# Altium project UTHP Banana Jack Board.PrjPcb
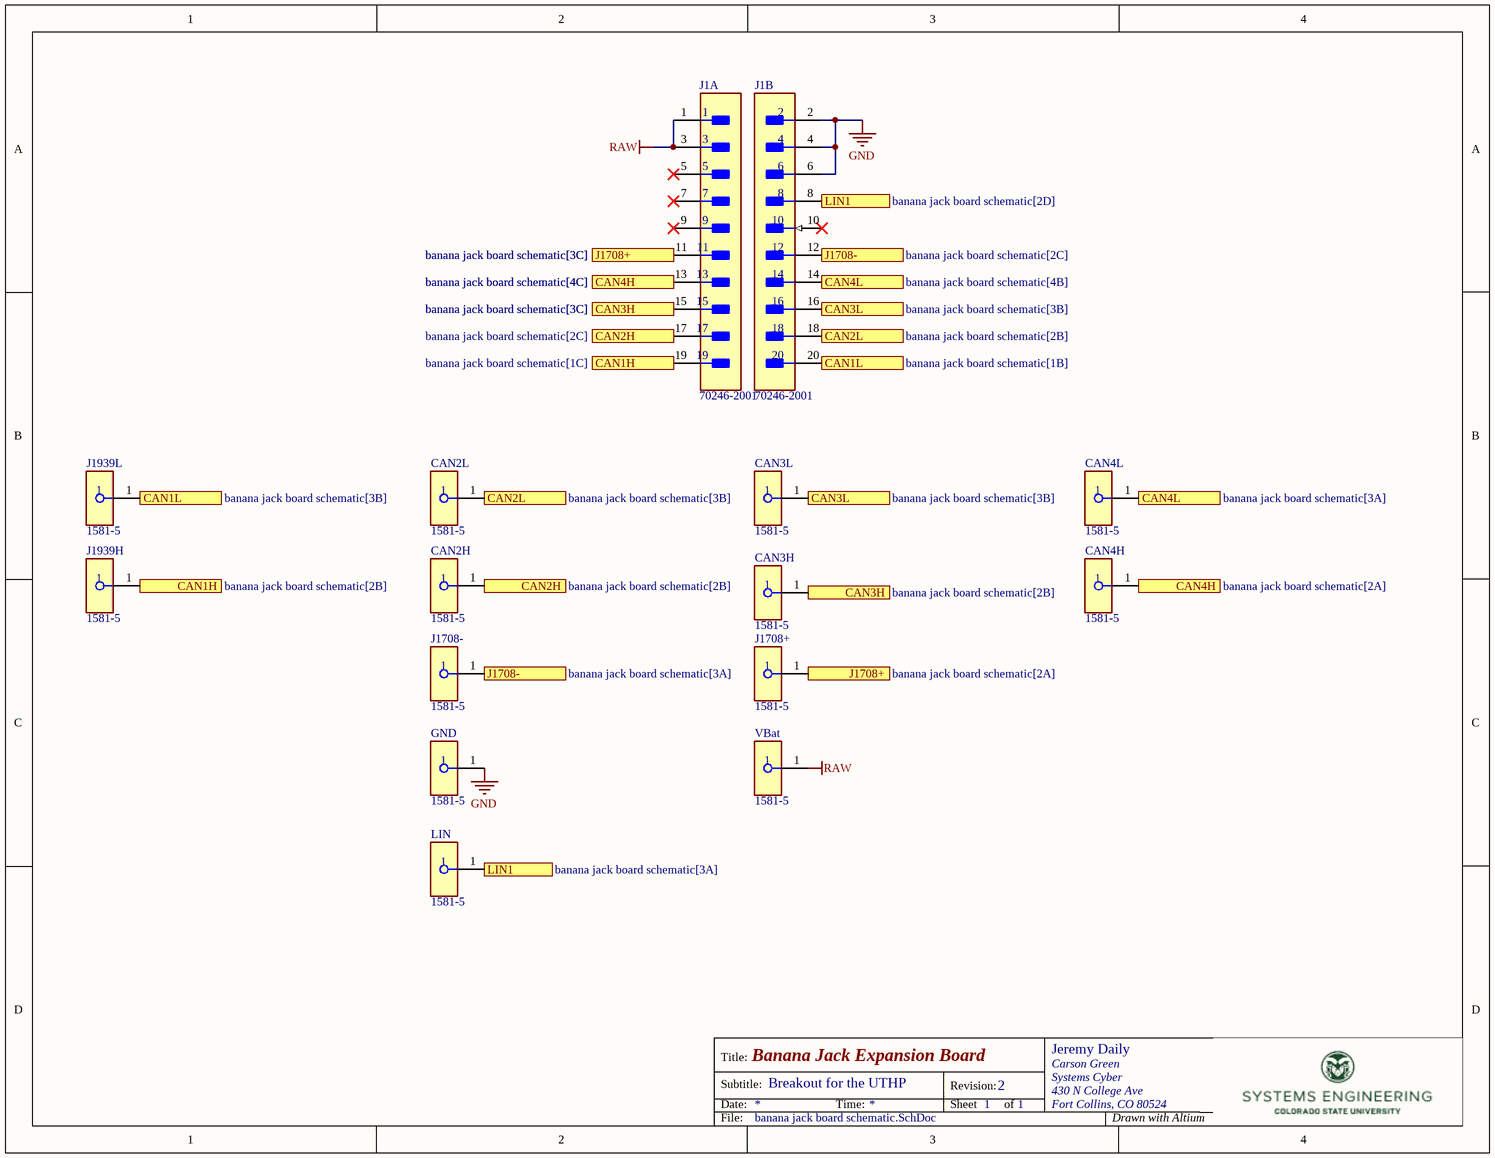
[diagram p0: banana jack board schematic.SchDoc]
1 sheet, 14 parts. Net scope: flat (ports and power ports of the same name join across sheets).
Board file: banana jack circuit board.PcbDoc

## Sheet banana jack board schematic.SchDoc: Banana Jack Expansion Board
size Letter; Author: Jeremy Daily; Organization: Carson Green; Address2: Systems Cyber; Address3: 430 N College Ave; Address4: Fort Collins, CO 80524; DocumentNumber: Breakout for the UTHP; Revision: 2; SheetNumber: 1; SheetTotal: 1

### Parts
CAN2H  1581-5  [FP-1581-5-MFG]
CAN2L  1581-5  [FP-1581-5-MFG]
CAN3H  1581-5  [FP-1581-5-MFG]
CAN3L  1581-5  [FP-1581-5-MFG]
CAN4H  1581-5  [FP-1581-5-MFG]
CAN4L  1581-5  [FP-1581-5-MFG]
GND  1581-5  [FP-1581-5-MFG]
J1  70246-2001  [FP-70246-2001-MFG]  (parts A,B of 2)
J1708+  1581-5  [FP-1581-5-MFG]
J1708-  1581-5  [FP-1581-5-MFG]
J1939H  1581-5  [FP-1581-5-MFG]
J1939L  1581-5  [FP-1581-5-MFG]
LIN  1581-5  [FP-1581-5-MFG]
VBat  1581-5  [FP-1581-5-MFG]

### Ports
CAN1H (see banana jack board schematic[1C]), CAN1H (see banana jack board schematic[2B]), CAN1L (see banana jack board schematic[1B]), CAN1L (see banana jack board schematic[3B]), CAN2H (see banana jack board schematic[2B]), CAN2H (see banana jack board schematic[2C]), CAN2L (see banana jack board schematic[2B]), CAN2L (see banana jack board schematic[3B]), CAN3H (see banana jack board schematic[2B]), CAN3H (see banana jack board schematic[3C]), CAN3L (see banana jack board schematic[3B]), CAN4H (see banana jack board schematic[2A]), CAN4H (see banana jack board schematic[4C]), CAN4L (see banana jack board schematic[3A]), CAN4L (see banana jack board schematic[4B]), J1708+ (see banana jack board schematic[2A]), J1708+ (see banana jack board schematic[3C]), J1708- (see banana jack board schematic[2C]), J1708- (see banana jack board schematic[3A]), LIN1 (see banana jack board schematic[2D]), LIN1 (see banana jack board schematic[3A])

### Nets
GND: GND.1 J1.2 J1.4 J1.6
RAW: J1.1 J1.3 VBat.1
NetCAN2H_1: CAN2H.1 J1.17 ; port CAN2H
NetCAN2L_1: CAN2L.1 J1.18 ; port CAN2L
NetCAN3H_1: CAN3H.1 J1.15 ; port CAN3H
NetCAN3L_1: CAN3L.1 J1.16 ; port CAN3L
NetCAN4H_1: CAN4H.1 J1.13 ; port CAN4H
NetCAN4L_1: CAN4L.1 J1.14 ; port CAN4L
NetJ1_8: J1.8 LIN.1 ; port LIN1
NetJ1_11: J1.11 J1708+.1 ; port J1708+
NetJ1_12: J1.12 J1708-.1 ; port J1708-
NetJ1_19: J1.19 J1939H.1 ; port CAN1H
NetJ1_20: J1.20 J1939L.1 ; port CAN1L

Not connected (* = marked no-connect by the designer): J1 5* 7* 9* 10*

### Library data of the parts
CAN2H CAN2L CAN3H CAN3L CAN4H CAN4L GND J1708+ J1708- J1939H J1939L LIN VBat = CMP-73906-000011-1: CONN BANANA JACK TURRET GREEN; Body Material: PC; Number of Contacts: 1; Max Current Rating: 15A; Voltage Rating (AC): 30V; Insulation: Mating End Insulated; Voltage Rating: 2.5kV; Voltage Rating (DC): 60V; Gender: Female
J1 = CMP-04776-001013-1: CONN HEADER VERT 20POS 2.54MM; Max Voltage Rating (AC): 250V; Gender: Male; Insulation Resistance: 12GR; Contact Resistance: 15mR; Max Current Rating: 2.5A; Number of Positions: 20; Glow Wire Compliant: Non-compliant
